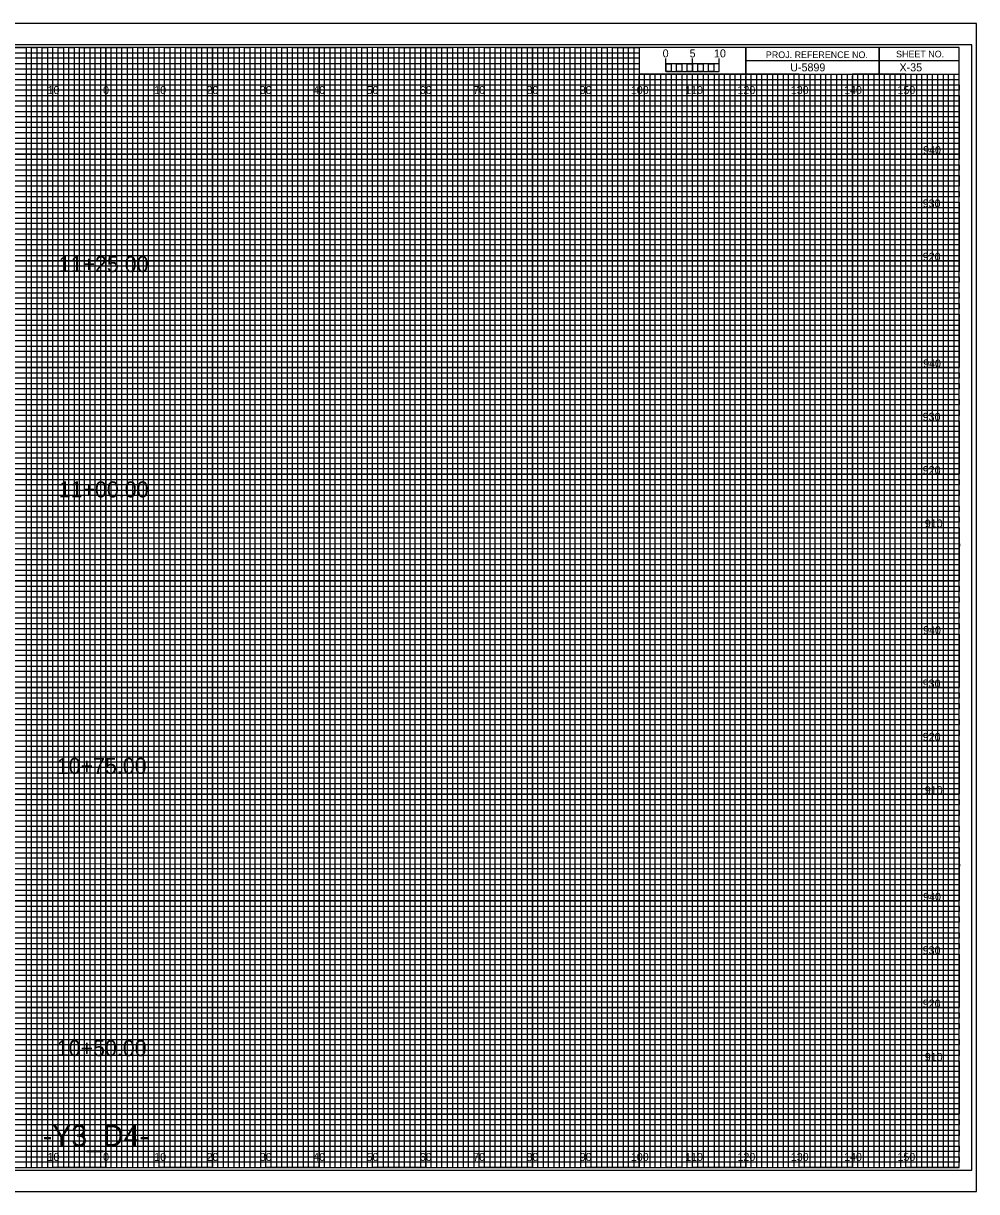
# Model space of a CAD drawing. Extents: x -13 to 323, y -4 to 214.
# Drawn here: x 144.5 to 323.3, y -4.5 to 214.5 of the extents above; entities that cross this region are included whole.
import ezdxf

# ---------------------------------------------------------------- set-up
doc = ezdxf.new("R2010")
doc.units = 0
for name, color, linetype in [('Prop XS Alignment Label', 7, 'Continuous'), ('Prop XS Bar Scale Labels', 7, 'Continuous'), ('Prop XS Elevation Labels', 7, 'Continuous'), ('Prop XS Offset Labels', 7, 'Continuous'), ('Prop XS Project Number', 7, 'Continuous'), ('Prop XS Sheet Number', 7, 'Continuous'), ('Prop XS Station Labels', 7, 'Continuous'), ('Sheet Cross Section CELL', 7, 'Continuous'), ('Sheet Cross Section Grid Major CELL', 7, 'Continuous'), ('Sheet Cross Section Grid Middle CELL', 7, 'Continuous'), ('Sheet Cross Section Grid Minor 1 CELL', 7, 'Continuous'), ('Sheet Cross Section Grid Minor 2 CELL', 7, 'Continuous'), ('Sheet Cross Section Scale CELL', 7, 'Continuous'), ('Sheet Cutting Line CELL', 7, 'Continuous'), ('Sheet DOT Grid CELL', 7, 'Continuous'), ('Sheet Plot Border Inside CELL', 7, 'Continuous'), ('Sheet Plot Border Outside CELL', 7, 'Continuous')]:
    doc.layers.add(name, color=color, linetype=linetype)

msp = doc.modelspace()

# ---------------------------------------------------------------- linework, layer by layer
at = {"layer": 'Sheet Cross Section CELL'}
for p, q in [((305, 210), (305, 205)), ((305, 205), (305, 210)), ((280, 207.5), (280, 205)), ((320, 207.49), (280, 207.49)), ((280, 205), (320, 205))]:
    msp.add_line(p, q, dxfattribs=at)
for points in [[(320, 210), (0, 210), (0, 0), (320, 0)], [(280, 210), (260, 210), (260, 205.03), (280, 205.03)], [(320, 210), (280, 210), (280, 205), (320, 205)]]:
    msp.add_lwpolyline(points, close=True, dxfattribs=at)
at = {"layer": 'Sheet Cross Section Grid Major CELL'}
for p, q in [((150, 210), (140, 210)), ((150, 0), (150, 210)), ((170, 210), (160, 210)), ((160, 210), (160, 0)), ((170, 0), (170, 210)), ((190, 210), (180, 210)), ((180, 210), (180, 0)), ((190, 0), (190, 210)), ((210, 210), (200, 210)), ((200, 210), (200, 0)), ((210, 0), (210, 210)), ((230, 210), (220, 210)), ((220, 210), (220, 0)), ((230, 0), (230, 210)), ((250, 210), (240, 210)), ((240, 210), (240, 0)), ((250, 0), (250, 210)), ((260, 210), (260, 0)), ((270, 0), (270, 205)), ((290, 205), (280, 205)), ((280, 205), (280, 0)), ((290, 0), (290, 205)), ((310, 205), (300, 205)), ((300, 205), (300, 0)), ((310, 0), (310, 205)), ((160, 0), (150, 0)), ((180, 0), (170, 0)), ((200, 0), (190, 0)), ((220, 0), (210, 0)), ((240, 0), (230, 0)), ((260, 0), (250, 0)), ((280, 0), (270, 0)), ((300, 0), (290, 0)), ((320, 0), (310, 0)), ((320, 0), (320, 0))]:
    msp.add_line(p, q, dxfattribs=at)
for points in [[(0, 200), (320, 200), (320, 190), (0, 190)], [(0, 180), (320, 180), (320, 170), (0, 170)], [(0, 160), (320, 160), (320, 150), (0, 150)], [(0, 140), (320, 140), (320, 130), (0, 130)], [(0, 120), (320, 120), (320, 110), (0, 110)], [(0, 100), (320, 100), (320, 90), (0, 90)], [(0, 80), (320, 80), (320, 70), (0, 70)], [(0, 60), (320, 60), (320, 50), (0, 50)], [(0, 40), (320, 40), (320, 30), (0, 30)], [(0, 20), (320, 20), (320, 10), (0, 10)]]:
    msp.add_lwpolyline(points, dxfattribs=at)
at = {"layer": 'Sheet Cross Section Grid Middle CELL'}
for points in [[(135, 210), (145, 210), (145, 0), (155, 0), (155, 210), (165, 210), (165, 0), (175, 0), (175, 210), (185, 210), (185, 0), (195, 0), (195, 210), (205, 210), (205, 0), (215, 0), (215, 210), (225, 210), (225, 0), (235, 0), (235, 210), (245, 210), (245, 0), (255, 0), (255, 210), (259.93, 210), (260, 210), (260, 205), (264.99, 205), (264.99, 0), (275, 0), (275, 205), (285, 205), (285, 0), (295, 0), (295, 205), (305, 205), (305, 0), (315, 0), (315, 205)], [(0, 205), (275, 205)], [(0, 185), (320, 185), (320, 195), (0, 195)], [(0, 165), (320, 165), (320, 175), (0, 175)], [(0, 145), (320, 145), (320, 155), (0, 155)], [(0, 125), (320, 125), (320, 135), (0, 135)], [(0, 105), (320, 105), (320, 115), (0, 115)], [(0, 85), (320, 85), (320, 95), (0, 95)], [(0, 65), (320, 65), (320, 75), (0, 75)], [(0, 45), (320, 45), (320, 55), (0, 55)], [(0, 25), (320, 25), (320, 35), (0, 35)], [(0, 5), (320, 5), (320, 15), (0, 15)]]:
    msp.add_lwpolyline(points, dxfattribs=at)
at = {"layer": 'Sheet Cross Section Grid Minor 1 CELL'}
for p, q in [((0, 209), (260, 209)), ((260, 209), (260, 207.98)), ((260, 207.98), (0, 207.98)), ((0, 207), (260, 207)), ((260, 205.89), (0, 205.89)), ((260, 207), (260, 205.89)), ((0, 204), (320, 204))]:
    msp.add_line(p, q, dxfattribs=at)
for points in [[(0, 203), (270, 203), (320, 203), (320, 202), (0, 202)], [(0, 201), (320, 201), (320, 199), (0, 199)], [(0, 198), (320, 198), (320, 197), (0, 196.98)], [(0, 196), (320, 196), (320, 194), (0, 194)], [(0, 193), (320, 193), (320, 192), (0, 192)], [(0, 191), (320, 191), (320, 189), (0, 189)], [(0, 188), (320, 188), (320, 187), (0, 187)], [(0, 186), (320, 186), (320, 184), (0, 184)], [(0, 183), (320, 183), (320, 182), (0, 182)], [(0, 181), (320, 181), (320, 179), (0, 179)], [(0, 178), (320, 178), (320, 177), (0, 177)], [(0, 176), (320, 176), (320, 173.95), (320, 173), (320, 172), (0, 172)], [(0, 174), (320, 174), (320, 173), (0, 173)], [(0, 171), (320, 171), (320, 169), (0, 169.03)], [(0, 169.03), (320, 169), (320, 168), (0, 168)], [(0, 167), (320, 167), (320, 166), (0, 166)], [(0, 164), (320, 164), (320, 163), (0, 163)], [(0, 162), (320, 162), (320, 161), (0, 161)], [(-0.07, 158.89), (320, 158.89), (320, 157.88), (-0.07, 157.88)], [(0, 157), (320, 157), (320, 156), (0, 156)], [(0, 154), (320, 154), (320, 153), (0, 153)], [(0, 152), (320, 152), (320, 151), (0, 151)], [(0, 149), (320, 149), (320, 148), (0, 148)], [(0, 147), (320, 147), (320, 146), (0, 146)], [(0, 144), (320, 144), (320, 143), (0, 143)], [(0, 142), (320, 142), (320, 141), (0, 141)], [(0, 139), (320, 139), (319.99, 137.98), (0, 138)], [(0, 137), (320, 137), (320, 136), (0, 136)], [(0, 134), (320, 134), (320, 133), (0, 133)], [(0, 132), (320, 132), (320, 131), (0, 131)], [(0, 129), (320, 129), (320, 128), (0, 128)], [(0, 127), (320, 127), (320, 126), (0, 126)], [(0, 124), (320, 124), (320, 123), (0, 123)], [(0, 122), (320, 122), (320, 121), (0, 121)], [(0, 119), (320, 119), (320, 118), (0, 118)], [(0, 116.99), (320.07, 116.91), (320, 116), (0, 116)], [(0, 114), (320, 114), (320, 113), (0, 113)], [(0, 112), (320, 112), (320, 111), (0, 111)], [(0, 109), (320, 109), (320, 108), (0, 108)], [(0, 107), (320, 107), (320, 106), (0, 106)], [(0, 104), (320, 104), (320, 103), (0, 103)], [(0, 102), (320, 102), (320, 101), (0, 101)], [(0, 99), (320, 99), (320, 98), (0, 98)], [(0, 97), (320, 97), (320, 96), (0, 96)], [(0, 94), (320, 94), (320, 93), (0, 93)], [(0, 92), (320, 92), (320, 91), (0, 91)], [(0, 89), (320, 89), (320, 88), (0, 88)], [(0, 87), (320, 87), (320, 86), (0, 86)], [(0, 84), (320, 84), (320, 83), (0, 83)], [(0, 82), (320, 82), (320, 81), (0, 81)], [(0, 79), (320, 79), (319.99, 77.98), (0, 78)], [(0, 77), (320, 77), (320, 76), (0, 76)], [(0, 74), (320, 74), (320, 73), (0, 73)], [(0, 72), (320, 72), (320, 71), (0, 71)], [(0, 69), (320, 69), (320, 68), (0, 68)], [(0, 67), (320, 67), (320, 66), (0, 66)], [(0, 64), (320, 64), (320, 63), (0, 63)], [(0, 62), (320, 62), (320, 61), (0, 61)], [(0, 59), (320, 59), (320, 58), (0, 58)], [(0, 56.99), (320.07, 56.91), (320, 56), (0, 56)], [(0, 54), (320, 54), (320, 53), (0, 53)], [(0, 52), (320, 52), (320, 51), (0, 51)], [(0, 49), (320, 49), (320, 48), (0, 48)], [(0, 47), (320, 47), (320, 46), (0, 46)], [(0, 44), (320, 44), (320, 43), (0, 43)], [(0, 42), (320, 42), (320, 41), (0, 41)], [(0, 39), (320, 39), (320, 38), (0, 38)], [(0, 37), (320, 37), (320, 36), (0, 36)], [(0, 34), (320, 34), (320, 33), (0, 33)], [(0, 32), (320, 32), (320, 31), (0, 31)], [(0, 29), (320, 29), (320, 28), (0, 28)], [(0, 27), (320, 27), (320, 26), (0, 26)], [(0, 24), (320, 24), (320, 23), (0, 23)], [(0, 22), (320, 22), (320, 21), (0, 21)], [(0, 19), (320, 19), (320, 18), (0, 18)], [(0, 17), (320, 17), (320, 16), (0, 16)], [(0, 14), (320, 14), (320, 13), (0, 13)], [(0, 12), (320, 12), (320, 11), (0, 11)], [(0, 9), (320, 9), (320, 8), (0, 8)], [(0, 7), (320, 7), (320, 6), (0, 6)], [(0, 4), (320, 4), (320, 3), (0, 3)], [(0, 2), (320, 2), (320, 1), (0, 1)]]:
    msp.add_lwpolyline(points, dxfattribs=at)
at = {"layer": 'Sheet Cross Section Grid Minor 2 CELL'}
for p, q in [((267, 205), (266.01, 205)), ((266.01, 205), (266.01, 0)), ((267, 0), (267, 205)), ((269, 205), (268, 205)), ((268, 205), (268, 0)), ((269, 0), (269, 205)), ((266.01, 0), (265, 0)), ((268, 0), (267, 0))]:
    msp.add_line(p, q, dxfattribs=at)
for points in [[(145, 0), (146, 0), (146, 210), (147, 210), (147, 0)], [(147, 0), (148, 0), (148, 210), (149, 210), (149, 0)], [(150, 0), (151, 0), (151, 210), (152, 210), (152, 0)], [(152, 0), (153, 0), (153, 210), (154, 210), (154, 0)], [(155, 0), (156, 0), (156, 210), (157, 210), (157, 0)], [(157, 0), (158, 0), (158, 210), (159, 210), (159, 0)], [(160, 0), (161, 0), (161, 210), (162, 210), (162, 0)], [(162, 0), (163, 0), (163, 210), (164, 210), (164, 0)], [(165, 0), (166, 0), (166, 210), (167, 210), (167, 0)], [(167, 0), (168, 0), (168, 210), (169, 210), (169, 0)], [(170, 0), (171, 0), (171, 210), (172, 210), (172, 0)], [(172, 0), (173, 0), (173, 210), (174, 210), (174, 0)], [(175, 0), (176, 0), (176, 210), (177, 210), (177, 0)], [(177, 0), (178, 0), (178, 210), (179, 210), (179, 0)], [(180, 0), (181, 0), (181, 210), (182, 210), (182, 0)], [(182, 0), (183, 0), (183, 210), (184, 210), (184, 0)], [(185, 0), (186, 0), (186, 210), (187, 210), (187, 0)], [(187, 0), (188, 0), (188, 210), (189, 210), (189, 0)], [(190, 0), (191, 0), (191, 210), (192, 210), (192, 0)], [(192, 0), (193, 0), (193, 210), (194, 210), (194, 0)], [(195, 0), (196, 0), (196, 210), (197, 210), (197, 0)], [(197, 0), (198, 0), (198, 210), (199, 210), (199, 0)], [(200, 0), (201, 0), (201, 210), (202, 210), (202, 0)], [(202, 0), (203, 0), (203, 210), (204, 210), (204, 0)], [(205, 0), (206, 0), (206, 210), (207, 210), (207, 0)], [(207, 0), (208, 0), (208, 210), (209, 210), (209, 0)], [(210, 0), (211, 0), (211, 210), (212, 210), (212, 0)], [(212, 0), (213, 0), (213, 210), (214, 210), (214, 0)], [(215, 0), (216, 0), (216, 210), (217, 210), (217, 0)], [(217, 0), (218, 0), (218, 210), (219, 210), (219, 0)], [(220, 0), (221, 0), (221, 210), (222, 210), (222, 0)], [(222, 0), (223, 0), (223, 210), (224, 210), (224, 0)], [(225, 0), (226, 0), (226, 210), (227, 210), (227, 0)], [(227, 0), (228, 0), (228, 210), (229, 210), (229, 0)], [(230, 0), (231, 0), (231, 210), (232, 210), (232, 0)], [(232, 0), (233, 0), (233, 210), (234, 210), (234, 0)], [(235, 0), (236, 0), (236, 210), (237, 210), (237, 0)], [(237, 0), (238, 0), (238, 210), (239, 210), (239, 0)], [(240, 0), (241, 0), (241, 210), (242, 210), (242, 0)], [(242, 0), (243, 0), (243, 210), (244, 210), (244, 0)], [(245, 0), (246, 0), (246, 210), (247, 210), (247, 0)], [(247, 0), (248, 0), (248, 210), (249, 210), (249, 0)], [(250, 0), (251, 0), (251, 210), (252, 210), (252, 0)], [(252, 0), (253, 0), (253, 210), (254, 210), (254, 0)], [(255, 0), (256, 0), (256, 210), (257, 210), (257, 0)], [(257, 0), (258, 0), (258, 210), (259, 210), (259, 0)], [(260, 0), (261, 0), (261, 205), (262.02, 205), (262.02, 0)], [(262, 0), (263, 0), (263, 205), (263.99, 205), (263.99, 0)], [(270, 0), (270.98, 0), (270.98, 205), (272, 205), (272, 0)], [(272, 0), (273, 0), (273, 205), (274.05, 205), (274.05, 0)], [(275, 0), (276, 0), (276, 205), (277, 205), (277, 0)], [(277, 0), (278, 0), (278, 205), (279, 205), (279, 0)], [(280, 0), (281, 0), (281, 205), (282, 205), (282, 0)], [(282, 0), (283, 0), (283, 205), (284, 205), (284, 0)], [(285, 0), (286, 0), (286, 205), (287, 205), (287, 0)], [(287, 0), (288, 0), (288, 205), (289, 205), (289, 0)], [(290, 0), (291, 0), (291, 205), (292, 205), (292, 0)], [(292, 0), (293, 0), (293, 205), (294, 205), (294, 0)], [(295, 0), (296, 0), (296, 205), (297, 205), (297, 0)], [(297, 0), (298, 0), (298, 205), (299, 205), (299, 0)], [(300, 0), (301, 0), (301, 205), (302, 205), (302, 0)], [(302, 0), (303, 0), (303, 205), (304, 205), (304, 0)], [(305, 0), (306, 0), (306, 205), (307, 205), (307, 0)], [(307, 0), (308, 0), (308, 205), (309, 205), (309, 0)], [(310, 0), (311, 0), (311, 205), (312, 205), (312, 0)], [(312, 0), (313, 0), (313, 205), (314, 205), (314, 0)], [(315, 0), (316, 0), (316, 205), (317, 205), (317, 0)], [(317, 0), (318, 0), (318, 205), (319, 205), (319, 0)]]:
    msp.add_lwpolyline(points, dxfattribs=at)
at = {"layer": 'Sheet Cross Section Scale CELL'}
for p, q in [((265, 205.49), (265, 207.9)), ((265, 206.9), (265, 207.9)), ((270, 205.49), (270, 207.9)), ((275, 205.49), (275, 207.9)), ((275, 206.9), (275, 207.9))]:
    msp.add_line(p, q, dxfattribs=at)
for points in [[(275, 206.9), (265, 206.9), (265, 205.49), (275, 205.49)], [(265, 206.9), (266, 206.9), (266, 205.49), (265, 205.49)], [(267, 206.9), (268, 206.9), (268, 205.49), (267, 205.49)], [(269, 206.9), (270, 206.9), (270, 205.49), (269, 205.49)], [(271, 206.9), (272, 206.9), (272, 205.49), (271, 205.49)], [(273, 206.9), (274, 206.9), (274, 205.49), (273, 205.49)]]:
    msp.add_lwpolyline(points, close=True, dxfattribs=at)
at = {"layer": 'Sheet Cutting Line CELL'}
for p, q in [((323.3, 214.5), (-13.4, 214.5)), ((-13.4, -4.5), (323.3, -4.5))]:
    msp.add_line(p, q, dxfattribs=at)
at = {"layer": 'Sheet DOT Grid CELL'}
for p, q in [((150, 0), (150, 210)), ((160, 0), (160, 210)), ((170, 0), (170, 210)), ((180, 0), (180, 210)), ((190, 0), (190, 210)), ((200, 0), (200, 210)), ((210, 0), (210, 210)), ((220, 0), (220, 210)), ((230, 0), (230, 210)), ((240, 0), (240, 210)), ((250, 0), (250, 210)), ((260, 0), (260, 204.69)), ((270, 0), (270, 204.69)), ((280, 0), (280, 204.69)), ((290, 0), (290, 204.69)), ((300, 0), (300, 204.69)), ((310, 0), (310, 204.69)), ((0, 200), (320, 200)), ((0, 190), (320, 190)), ((0, 180), (320, 180)), ((0, 170), (320, 170)), ((0, 160), (320, 160)), ((0, 150), (320, 150)), ((0, 140), (320, 140)), ((0, 130), (320, 130)), ((0, 120), (320, 120)), ((0, 110), (320, 110)), ((0, 100), (320, 100)), ((0, 90), (320, 90)), ((0, 80), (320, 80)), ((0, 70), (320, 70)), ((0, 60), (320, 60)), ((0, 50), (320, 50)), ((0, 40), (320, 40)), ((0, 30), (320, 30)), ((0, 20), (320, 20)), ((0, 10), (320, 10))]:
    msp.add_line(p, q, dxfattribs=at)
at = {"layer": 'Sheet Plot Border Inside CELL'}
msp.add_lwpolyline([(-10.8, -0.5), (322.4, -0.5), (322.4, 210.5), (-10.8, 210.5)], close=True, dxfattribs=at)
at = {"layer": 'Sheet Plot Border Outside CELL'}
msp.add_lwpolyline([(-13.4, -4.5), (323.3, -4.5), (323.3, 214.5), (-13.4, 214.5)], close=True, dxfattribs=at)

# ---------------------------------------------------------------- texts
at = {"layer": 'Prop XS Alignment Label'}
msp.add_text('-Y3_D4-', height=4, dxfattribs=at).set_placement((148.14, 4))
at = {"layer": 'Prop XS Bar Scale Labels'}
for s, p in [('5', (269.47, 208.12)), ('10', (274.04, 208.12))]:
    msp.add_text(s, height=1.5, dxfattribs=at).set_placement(p)
at = {"layer": 'Prop XS Elevation Labels'}
for s, p in [('940', (313.26, 190)), ('930', (313.18, 180)), ('920', (313.19, 170)), ('940', (313.26, 150)), ('930', (313.18, 140)), ('920', (313.19, 130)), ('910', (313.57, 120)), ('940', (313.26, 100)), ('930', (313.18, 90)), ('920', (313.19, 80)), ('910', (313.57, 70)), ('940', (313.26, 50)), ('930', (313.18, 40)), ('920', (313.19, 30)), ('910', (313.57, 20))]:
    msp.add_text(s, height=1.5, dxfattribs=at).set_placement(p)
at = {"layer": 'Prop XS Offset Labels'}
for s, p in [('10', (149.04, 201.25)), ('0', (159.45, 201.25)), ('0', (159.45, 201.25)), ('10', (169.04, 201.25)), ('20', (178.86, 201.25)), ('30', (188.86, 201.25)), ('40', (198.86, 201.25)), ('50', (208.86, 201.25)), ('60', (218.86, 201.25)), ('70', (228.86, 201.25)), ('80', (238.86, 201.25)), ('90', (248.86, 201.25)), ('100', (258.44, 201.25)), ('110', (268.62, 201.25)), ('120', (278.44, 201.25)), ('130', (288.44, 201.25)), ('140', (298.44, 201.25)), ('150', (308.44, 201.25)), ('10', (149.04, 1.25)), ('0', (159.45, 1.25)), ('0', (159.45, 1.25)), ('10', (169.04, 1.25)), ('20', (178.86, 1.25)), ('30', (188.86, 1.25)), ('40', (198.86, 1.25)), ('50', (208.86, 1.25)), ('60', (218.86, 1.25)), ('70', (228.86, 1.25)), ('80', (238.86, 1.25)), ('90', (248.86, 1.25)), ('100', (258.44, 1.25)), ('110', (268.62, 1.25)), ('120', (278.44, 1.25)), ('130', (288.44, 1.25)), ('140', (298.44, 1.25)), ('150', (308.44, 1.25))]:
    msp.add_text(s, height=1.5, dxfattribs=at).set_placement(p)
at = {"layer": 'Prop XS Project Number'}
msp.add_text('U-5899', height=1.5, dxfattribs=at).set_placement((288.34, 205.5))
at = {"layer": 'Prop XS Sheet Number'}
msp.add_text('X-35', height=1.5, dxfattribs=at).set_placement((308.83, 205.5))
at = {"layer": 'Prop XS Station Labels'}
for s, p in [('11+25.00', (151.13, 167.88)), ('11+00.00', (151.13, 125.64)), ('10+75.00', (150.77, 73.8)), ('10+50.00', (150.77, 20.91))]:
    msp.add_text(s, height=3, dxfattribs=at).set_placement(p)
at = {"layer": 'Sheet Cross Section CELL'}
for s, p in [('PROJ. REFERENCE NO.', (283.77, 207.99)), ('SHEET NO.', (308.19, 208.12))]:
    msp.add_text(s, height=1.25, dxfattribs=at).set_placement(p)
at = {"layer": 'Sheet Cross Section Scale CELL'}
msp.add_text('0', height=1.5, dxfattribs=at).set_placement((264.41, 208.12))

doc.saveas('drawing.dxf')
